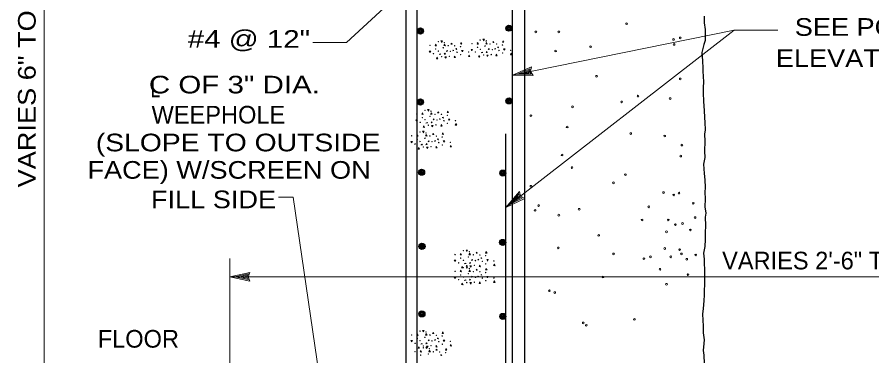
# Model space of a CAD drawing. Extents: x -28.1 to 13.9, y -16.1 to 13.9.
# Drawn here: x -10.39 to -4.33, y -8.27 to -5.87 of the extents above; entities that cross this region are included whole.
import ezdxf
from ezdxf.enums import TextEntityAlignment as Align

# ---------------------------------------------------------------- set-up
doc = ezdxf.new("R2010")
doc.units = 0
doc.header["$LTSCALE"] = 0.05
doc.layers.add('1', color=7, linetype='Continuous', lineweight=13)
doc.layers.add('2', color=7, linetype='Continuous', lineweight=13)

msp = doc.modelspace()

# ---------------------------------------------------------------- linework, layer by layer
at = {"layer": '1', "lineweight": 25}
for p, q in [((-7.63204, -10.78531), (-7.63204, -2.71131)), ((-6.79104, -10.78531), (-6.79104, -2.71131)), ((-6.87804, -10.71531), (-6.87804, -2.77031)), ((-7.55404, -10.70931), (-7.55404, -2.79231)), ((-6.92404, -10.72031), (-6.92404, -6.69531))]:
    msp.add_line(p, q, dxfattribs=at)
at = {"layer": '1'}
for p, q in [((-6.87804, -6.28131), (-5.30604, -5.96131)), ((-6.87804, -6.28131), (-6.74304, -6.22231)), ((-6.84204, -6.27431), (-6.75404, -6.23531)), ((-6.75404, -6.23531), (-6.75804, -6.25731)), ((-6.87804, -6.28131), (-6.73104, -6.28331)), ((-6.84204, -6.27431), (-6.74604, -6.27431)), ((-6.80604, -6.26631), (-6.76404, -6.24831)), ((-6.80604, -6.26631), (-6.76104, -6.26631)), ((-6.76404, -6.24831), (-6.76604, -6.25831)), ((-6.76604, -6.25831), (-6.76104, -6.26631)), ((-6.75804, -6.25731), (-6.74604, -6.27431)), ((-8.53504, -7.14431), (-8.43204, -7.14431)), ((-8.43204, -7.14431), (-8.06504, -9.66431)), ((-6.92404, -7.21731), (-6.82904, -7.10431)), ((-6.89504, -7.19431), (-6.83304, -7.12131)), ((-6.86604, -7.17231), (-6.83704, -7.13731)), ((-6.83704, -7.13731), (-6.83404, -7.14731)), ((-6.83404, -7.14731), (-6.82504, -7.15231)), ((-6.83304, -7.12131), (-6.82804, -7.14231)), ((-6.82804, -7.14231), (-6.80804, -7.15231)), ((-6.92404, -7.21731), (-6.79104, -7.15331)), ((-6.89504, -7.19431), (-6.80804, -7.15231)), ((-6.86604, -7.17231), (-6.82504, -7.15231)), ((-8.88204, -10.58231), (-8.88204, -7.58031)), ((-8.88204, -7.70831), (-8.73804, -7.67731)), ((-8.84504, -7.70831), (-8.75104, -7.68831)), ((-8.75104, -7.68831), (-8.76004, -7.70831)), ((-8.88204, -7.70831), (-2.77004, -7.70831)), ((-8.88204, -7.70831), (-8.73804, -7.73931)), ((-8.84504, -7.70831), (-8.75104, -7.72831)), ((-8.80904, -7.70831), (-8.76404, -7.69831)), ((-8.80904, -7.70831), (-8.76404, -7.71731)), ((-8.76404, -7.69831), (-8.76804, -7.70831)), ((-8.76804, -7.70831), (-8.76404, -7.71731)), ((-8.76004, -7.70831), (-8.75104, -7.72831))]:
    msp.add_line(p, q, dxfattribs=at)
for points in [[(-10.19604, -11.70431), (-10.19604, -9.90431), (-10.19604, -2.71031)], [(-8.29204, -6.04931), (-8.05404, -6.04931), (-7.55404, -5.58731), (-7.63904, -5.70731)], [(-6.92404, -7.21731), (-5.30604, -5.96131), (-4.99804, -5.96131)], [(-6.74304, -6.22231), (-6.75104, -6.25531), (-6.73104, -6.28331)], [(-6.82904, -7.10431), (-6.82104, -7.13731), (-6.79104, -7.15331)], [(-8.73804, -7.67731), (-8.75204, -7.70831), (-8.73804, -7.73931)]]:
    msp.add_lwpolyline(points, dxfattribs=at)
at = {"layer": '1', "lineweight": 25}
for points in [[(-5.52004, -5.86431), (-5.51904, -5.90931), (-5.51304, -5.95831), (-5.51204, -5.99531), (-5.51204, -6.03531), (-5.52204, -6.06331), (-5.53504, -6.12031), (-5.53104, -6.17831), (-5.52904, -6.23031), (-5.52904, -6.25231)], [(-5.52904, -6.25231), (-5.52304, -6.32731), (-5.52604, -6.36831), (-5.52504, -6.40631), (-5.52304, -6.46731), (-5.51904, -6.53231), (-5.51704, -6.58031), (-5.51504, -6.61731), (-5.51204, -6.66831), (-5.51604, -6.69931), (-5.51504, -6.74831), (-5.51604, -6.82031), (-5.51504, -6.86431), (-5.52304, -6.91131), (-5.52004, -6.97631), (-5.51404, -7.02131), (-5.51204, -7.07631), (-5.51404, -7.10831), (-5.51304, -7.15631), (-5.51404, -7.21231), (-5.50804, -7.25931), (-5.51104, -7.28631), (-5.51004, -7.34631), (-5.51204, -7.39731), (-5.51204, -7.44531), (-5.51504, -7.49331), (-5.52304, -7.54131), (-5.51904, -7.58431), (-5.51804, -7.62031), (-5.51604, -7.65331), (-5.51704, -7.70831), (-5.51704, -7.76231), (-5.51804, -7.80631), (-5.52004, -7.83631), (-5.52204, -7.87931), (-5.52704, -7.93331), (-5.53004, -7.97331), (-5.52904, -8.01531), (-5.52704, -8.05831), (-5.52704, -8.10531), (-5.52004, -8.15431), (-5.52204, -8.18131), (-5.52604, -8.23131), (-5.52204, -8.26331), (-5.52004, -8.32331)]]:
    msp.add_lwpolyline(points, dxfattribs=at)
for centre, radius in [((-6.90299, -5.94823), 0.02168), ((-6.90299, -5.94823), 0.01681), ((-6.90299, -5.94823), 0.01233), ((-7.52999, -5.96823), 0.02168), ((-7.52999, -5.96823), 0.01681), ((-7.52999, -5.96823), 0.01233), ((-7.52999, -5.96823), 0.00623), ((-6.90299, -5.94823), 0.00623), ((-7.52999, -6.47123), 0.02168), ((-7.52999, -6.47123), 0.01681), ((-7.52999, -6.47123), 0.01233), ((-7.52999, -6.47123), 0.00623), ((-6.90199, -6.46323), 0.02168), ((-6.90199, -6.46323), 0.01681), ((-6.90199, -6.46323), 0.01233), ((-6.90199, -6.46323), 0.00623), ((-7.52199, -6.96823), 0.02168), ((-7.52199, -6.96823), 0.01681), ((-7.52199, -6.96823), 0.01233), ((-7.52199, -6.96823), 0.00623), ((-6.94599, -6.97423), 0.02168), ((-6.94599, -6.97423), 0.01681), ((-6.94599, -6.97423), 0.01233), ((-6.94599, -6.97423), 0.00623), ((-6.94699, -7.46523), 0.02168), ((-6.94699, -7.46523), 0.01681), ((-7.51899, -7.49323), 0.02168), ((-7.51899, -7.49323), 0.01681), ((-7.51899, -7.49323), 0.01233), ((-7.51899, -7.49323), 0.00623), ((-6.94699, -7.46523), 0.01233), ((-6.94699, -7.46523), 0.00623), ((-7.51999, -7.97123), 0.02168), ((-7.51999, -7.97123), 0.01681), ((-7.51999, -7.97123), 0.01233), ((-7.51999, -7.97123), 0.00623), ((-6.94599, -7.98923), 0.02168), ((-6.94599, -7.98923), 0.01681), ((-6.94599, -7.98923), 0.01233), ((-6.94599, -7.98923), 0.00623)]:
    msp.add_circle(centre, radius, dxfattribs=at)
at = {"layer": '1'}
for centre in [(-6.06904, -5.91631), (-6.71204, -5.97431), (-6.54904, -5.97431), (-5.73604, -6.02831), (-5.73204, -6.06331), (-5.68904, -6.01731), (-6.57204, -6.11031), (-6.32404, -6.07931), (-6.28204, -6.28831), (-5.68904, -6.30731), (-6.10404, -6.47031), (-5.98804, -6.42931), (-5.76004, -6.44631), (-6.45204, -6.50531), (-6.74704, -6.56731), (-6.49004, -6.64831), (-6.03904, -6.69431), (-5.79804, -6.71131), (-5.67704, -6.77631), (-6.52604, -6.84631), (-5.68504, -6.85431), (-6.45604, -6.93531), (-6.07704, -6.98531), (-6.74704, -7.06731), (-6.16204, -7.04331), (-5.80704, -7.11231), (-5.73504, -7.12931), (-5.69704, -7.11631), (-6.69204, -7.20431), (-5.91204, -7.21331), (-5.59604, -7.18831), (-6.71704, -7.23831), (-6.54904, -7.27231), (-6.40504, -7.23031), (-5.95904, -7.30631), (-5.77304, -7.30631), (-5.67204, -7.33131), (-5.58304, -7.28931), (-5.78604, -7.39031), (-5.72304, -7.33931), (-5.61704, -7.37731), (-6.26604, -7.41531), (-6.55304, -7.50431), (-5.79804, -7.50831), (-5.69304, -7.51631), (-6.16104, -7.54631), (-5.90004, -7.56731), (-5.75604, -7.56731), (-5.68004, -7.54631), (-5.57904, -7.55431), (-5.94604, -7.58031), (-5.64204, -7.58431), (-5.83204, -7.65531), (-5.63404, -7.69331), (-6.23704, -7.71031), (-6.61604, -7.80731), (-6.57804, -7.82031), (-5.78604, -7.76131), (-6.37604, -8.03531), (-6.35504, -8.05231), (-6.01304, -8.01031)]:
    msp.add_circle(centre, 0.006, dxfattribs=at)
at = {"layer": '2'}
for p, q in [((-7.31404, -6.05931), (-7.30804, -6.05431)), ((-7.01704, -6.04731), (-7.01104, -6.04231)), ((-7.40804, -6.54531), (-7.40204, -6.54031)), ((-7.44404, -6.69931), (-7.43804, -6.69431)), ((-7.13604, -7.54031), (-7.13004, -7.53531)), ((-7.13604, -7.65931), (-7.13004, -7.65431)), ((-7.44404, -8.10931), (-7.43804, -8.10431)), ((-7.42004, -8.22731), (-7.41404, -8.22231))]:
    msp.add_line(p, q, dxfattribs=at)
for points in [[(-7.38004, -6.04731), (-7.38504, -6.03831), (-7.37404, -6.03831), (-7.38004, -6.04931)], [(-7.30804, -6.05431), (-7.30604, -6.06131), (-7.31404, -6.06131)], [(-7.24104, -6.04931), (-7.24604, -6.05931), (-7.23604, -6.06031), (-7.24404, -6.04931)], [(-7.12404, -6.05031), (-7.12904, -6.06031), (-7.11904, -6.06131), (-7.12704, -6.05031)], [(-7.08304, -6.03531), (-7.08804, -6.02631), (-7.07704, -6.02631), (-7.08304, -6.03731)], [(-7.06204, -6.04931), (-7.06704, -6.05931), (-7.05604, -6.06031), (-7.06404, -6.04931)], [(-7.01104, -6.04231), (-7.00904, -6.04931), (-7.01704, -6.04931)], [(-6.94404, -6.03731), (-6.94904, -6.04731), (-6.93904, -6.04831), (-6.94704, -6.03731)], [(-7.46304, -6.11831), (-7.46804, -6.11031), (-7.45704, -6.11031), (-7.46304, -6.12031)], [(-7.42104, -6.06231), (-7.42604, -6.07231), (-7.41604, -6.07331), (-7.42404, -6.06231)], [(-7.35904, -6.06131), (-7.36404, -6.07131), (-7.35304, -6.07231), (-7.36104, -6.06131)], [(-7.30104, -6.10731), (-7.29804, -6.10331), (-7.29304, -6.10731), (-7.30004, -6.10831)], [(-7.28104, -6.09431), (-7.27604, -6.09231), (-7.27304, -6.09831), (-7.28104, -6.09531)], [(-7.23304, -6.11431), (-7.23804, -6.10631), (-7.22704, -6.10631), (-7.23304, -6.11631)], [(-7.16604, -6.10631), (-7.17104, -6.09831), (-7.16004, -6.09831), (-7.16604, -6.10831)], [(-7.09704, -6.12131), (-7.09204, -6.11831), (-7.08804, -6.12131), (-7.10004, -6.12331)], [(-7.00404, -6.09531), (-7.00104, -6.09131), (-6.99604, -6.09531), (-7.00304, -6.09631)], [(-6.98404, -6.08231), (-6.97904, -6.08031), (-6.97604, -6.08631), (-6.98404, -6.08331)], [(-6.93604, -6.10231), (-6.94104, -6.09431), (-6.93004, -6.09431), (-6.93604, -6.10431)], [(-7.41104, -6.15431), (-7.41604, -6.16431), (-7.40604, -6.16531), (-7.41404, -6.15431)], [(-7.39404, -6.13331), (-7.38904, -6.13031), (-7.38504, -6.13331), (-7.39704, -6.13531)], [(-7.35204, -6.15931), (-7.35704, -6.15031), (-7.34604, -6.15031), (-7.35204, -6.16031)], [(-7.28704, -6.14531), (-7.29204, -6.15531), (-7.28204, -6.15631), (-7.29004, -6.14531)], [(-7.18404, -6.13831), (-7.18904, -6.14831), (-7.17904, -6.14931), (-7.18604, -6.13831)], [(-7.11404, -6.14231), (-7.11904, -6.15231), (-7.10904, -6.15331), (-7.11704, -6.14231)], [(-7.05504, -6.14731), (-7.06004, -6.13831), (-7.04904, -6.13831), (-7.05504, -6.14831)], [(-6.99004, -6.13331), (-6.99504, -6.14331), (-6.98504, -6.14431), (-6.99304, -6.13331)], [(-6.88704, -6.12631), (-6.89204, -6.13631), (-6.88204, -6.13731), (-6.88904, -6.12631)], [(-7.47404, -6.53331), (-7.47904, -6.52431), (-7.46804, -6.52431), (-7.47404, -6.53531)], [(-7.40204, -6.54031), (-7.40004, -6.54731), (-7.40804, -6.54731)], [(-7.33504, -6.53531), (-7.34004, -6.54531), (-7.33004, -6.54631), (-7.33804, -6.53531)], [(-7.55704, -6.60431), (-7.56204, -6.59631), (-7.55104, -6.59631), (-7.55704, -6.60631)], [(-7.51504, -6.54831), (-7.52004, -6.55831), (-7.51004, -6.55931), (-7.51804, -6.54831)], [(-7.45304, -6.54731), (-7.45804, -6.55731), (-7.44704, -6.55831), (-7.45504, -6.54731)], [(-7.39504, -6.59331), (-7.39204, -6.58931), (-7.38704, -6.59331), (-7.39404, -6.59431)], [(-7.37504, -6.58031), (-7.37004, -6.57831), (-7.36704, -6.58431), (-7.37504, -6.58131)], [(-7.32704, -6.60031), (-7.33204, -6.59231), (-7.32104, -6.59231), (-7.32704, -6.60231)], [(-7.50504, -6.64031), (-7.51004, -6.65031), (-7.50004, -6.65131), (-7.50804, -6.64031)], [(-7.48804, -6.61931), (-7.48304, -6.61631), (-7.47904, -6.61931), (-7.49104, -6.62131)], [(-7.44604, -6.64531), (-7.45104, -6.63631), (-7.44004, -6.63631), (-7.44604, -6.64631)], [(-7.38104, -6.63131), (-7.38604, -6.64131), (-7.37604, -6.64231), (-7.38404, -6.63131)], [(-7.27804, -6.62431), (-7.28304, -6.63431), (-7.27304, -6.63531), (-7.28004, -6.62431)], [(-7.55104, -6.70231), (-7.55604, -6.71231), (-7.54604, -6.71331), (-7.55404, -6.70231)], [(-7.51004, -6.68731), (-7.51504, -6.67831), (-7.50404, -6.67831), (-7.51004, -6.68931)], [(-7.48904, -6.70131), (-7.49404, -6.71131), (-7.48304, -6.71231), (-7.49104, -6.70131)], [(-7.43804, -6.69431), (-7.43604, -6.70131), (-7.44404, -6.70131)], [(-7.37104, -6.68931), (-7.37604, -6.69931), (-7.36604, -6.70031), (-7.37404, -6.68931)], [(-7.59304, -6.75831), (-7.59804, -6.75031), (-7.58704, -6.75031), (-7.59304, -6.76031)], [(-7.52404, -6.77331), (-7.51904, -6.77031), (-7.51504, -6.77331), (-7.52704, -6.77531)], [(-7.43104, -6.74731), (-7.42804, -6.74331), (-7.42304, -6.74731), (-7.43004, -6.74831)], [(-7.41704, -6.78531), (-7.42204, -6.79531), (-7.41204, -6.79631), (-7.42004, -6.78531)], [(-7.41104, -6.73431), (-7.40604, -6.73231), (-7.40304, -6.73831), (-7.41104, -6.73531)], [(-7.36304, -6.75431), (-7.36804, -6.74631), (-7.35704, -6.74631), (-7.36304, -6.75631)], [(-7.31404, -6.77831), (-7.31904, -6.78831), (-7.30904, -6.78931), (-7.31604, -6.77831)], [(-7.54104, -6.79431), (-7.54604, -6.80431), (-7.53604, -6.80531), (-7.54404, -6.79431)], [(-7.48204, -6.79931), (-7.48704, -6.79031), (-7.47604, -6.79031), (-7.48204, -6.80031)], [(-7.24304, -7.54331), (-7.24804, -7.55331), (-7.23804, -7.55431), (-7.24604, -7.54331)], [(-7.20204, -7.52831), (-7.20704, -7.51931), (-7.19604, -7.51931), (-7.20204, -7.53031)], [(-7.18104, -7.54231), (-7.18604, -7.55231), (-7.17504, -7.55331), (-7.18304, -7.54231)], [(-7.13004, -7.53531), (-7.12804, -7.54231), (-7.13604, -7.54231)], [(-7.06304, -7.53031), (-7.06804, -7.54031), (-7.05804, -7.54131), (-7.06604, -7.53031)], [(-7.28504, -7.59931), (-7.29004, -7.59131), (-7.27904, -7.59131), (-7.28504, -7.60131)], [(-7.21604, -7.61431), (-7.21104, -7.61131), (-7.20704, -7.61431), (-7.21904, -7.61631)], [(-7.17404, -7.64031), (-7.17904, -7.63131), (-7.16804, -7.63131), (-7.17404, -7.64131)], [(-7.12304, -7.58831), (-7.12004, -7.58431), (-7.11504, -7.58831), (-7.12204, -7.58931)], [(-7.10904, -7.62631), (-7.11404, -7.63631), (-7.10404, -7.63731), (-7.11204, -7.62631)], [(-7.10304, -7.57531), (-7.09804, -7.57331), (-7.09504, -7.57931), (-7.10304, -7.57631)], [(-7.05504, -7.59531), (-7.06004, -7.58731), (-7.04904, -7.58731), (-7.05504, -7.59731)], [(-7.00604, -7.61931), (-7.01104, -7.62931), (-7.00104, -7.63031), (-7.00804, -7.61931)], [(-7.24304, -7.66231), (-7.24804, -7.67231), (-7.23804, -7.67331), (-7.24604, -7.66231)], [(-7.23304, -7.63531), (-7.23804, -7.64531), (-7.22804, -7.64631), (-7.23604, -7.63531)], [(-7.20204, -7.64731), (-7.20704, -7.63831), (-7.19604, -7.63831), (-7.20204, -7.64931)], [(-7.18104, -7.66131), (-7.18604, -7.67131), (-7.17504, -7.67231), (-7.18304, -7.66131)], [(-7.13004, -7.65431), (-7.12804, -7.66131), (-7.13604, -7.66131)], [(-7.10304, -7.69431), (-7.09804, -7.69231), (-7.09504, -7.69831), (-7.10304, -7.69531)], [(-7.06304, -7.64931), (-7.06804, -7.65931), (-7.05804, -7.66031), (-7.06604, -7.64931)], [(-7.28504, -7.71831), (-7.29004, -7.71031), (-7.27904, -7.71031), (-7.28504, -7.72031)], [(-7.23304, -7.75431), (-7.23804, -7.76431), (-7.22804, -7.76531), (-7.23604, -7.75431)], [(-7.21604, -7.73331), (-7.21104, -7.73031), (-7.20704, -7.73331), (-7.21904, -7.73531)], [(-7.17404, -7.75931), (-7.17904, -7.75031), (-7.16804, -7.75031), (-7.17404, -7.76031)], [(-7.12304, -7.70731), (-7.12004, -7.70331), (-7.11504, -7.70731), (-7.12204, -7.70831)], [(-7.10904, -7.74531), (-7.11404, -7.75531), (-7.10404, -7.75631), (-7.11204, -7.74531)], [(-7.05504, -7.71431), (-7.06004, -7.70631), (-7.04904, -7.70631), (-7.05504, -7.71631)], [(-7.00604, -7.73831), (-7.01104, -7.74831), (-7.00104, -7.74931), (-7.00804, -7.73831)], [(-7.55104, -8.11231), (-7.55604, -8.12231), (-7.54604, -8.12331), (-7.55404, -8.11231)], [(-7.51004, -8.09731), (-7.51504, -8.08831), (-7.50404, -8.08831), (-7.51004, -8.09931)], [(-7.48904, -8.11131), (-7.49404, -8.12131), (-7.48304, -8.12231), (-7.49104, -8.11131)], [(-7.43804, -8.10431), (-7.43604, -8.11131), (-7.44404, -8.11131)], [(-7.37104, -8.09931), (-7.37604, -8.10931), (-7.36604, -8.11031), (-7.37404, -8.09931)], [(-7.59304, -8.16831), (-7.59804, -8.16031), (-7.58704, -8.16031), (-7.59304, -8.17031)], [(-7.43104, -8.15731), (-7.42804, -8.15331), (-7.42304, -8.15731), (-7.43004, -8.15831)], [(-7.41104, -8.14431), (-7.40604, -8.14231), (-7.40304, -8.14831), (-7.41104, -8.14531)], [(-7.36304, -8.16431), (-7.36804, -8.15631), (-7.35704, -8.15631), (-7.36304, -8.16631)], [(-7.54104, -8.20431), (-7.54604, -8.21431), (-7.53604, -8.21531), (-7.54404, -8.20431)], [(-7.52704, -8.23031), (-7.53204, -8.24031), (-7.52204, -8.24131), (-7.53004, -8.23031)], [(-7.52404, -8.18331), (-7.51904, -8.18031), (-7.51504, -8.18331), (-7.52704, -8.18531)], [(-7.48604, -8.21531), (-7.49104, -8.20631), (-7.48004, -8.20631), (-7.48604, -8.21731)], [(-7.48204, -8.20931), (-7.48704, -8.20031), (-7.47604, -8.20031), (-7.48204, -8.21031)], [(-7.46504, -8.22931), (-7.47004, -8.23931), (-7.45904, -8.24031), (-7.46704, -8.22931)], [(-7.41704, -8.19531), (-7.42204, -8.20531), (-7.41204, -8.20631), (-7.42004, -8.19531)], [(-7.41404, -8.22231), (-7.41204, -8.22931), (-7.42004, -8.22931)], [(-7.34704, -8.21731), (-7.35204, -8.22731), (-7.34204, -8.22831), (-7.35004, -8.21731)], [(-7.31404, -8.18831), (-7.31904, -8.19831), (-7.30904, -8.19931), (-7.31604, -8.18831)], [(-7.38704, -8.26231), (-7.38204, -8.26031), (-7.37904, -8.26631), (-7.38704, -8.26331)]]:
    msp.add_lwpolyline(points, dxfattribs=at)
for points in [[(-7.34604, -6.11231), (-7.34104, -6.10331), (-7.33804, -6.10931)], [(-7.06404, -6.12131), (-7.05904, -6.11331), (-7.05604, -6.11931)], [(-7.04904, -6.10031), (-7.04404, -6.09131), (-7.04104, -6.09731)], [(-7.36104, -6.13331), (-7.35604, -6.12531), (-7.35304, -6.13131)], [(-7.44004, -6.59831), (-7.43504, -6.58931), (-7.43204, -6.59531)], [(-7.45504, -6.61931), (-7.45004, -6.61131), (-7.44704, -6.61731)], [(-7.49104, -6.77331), (-7.48604, -6.76531), (-7.48304, -6.77131)], [(-7.47604, -6.75231), (-7.47104, -6.74331), (-7.46804, -6.74931)], [(-7.18304, -7.61431), (-7.17804, -7.60631), (-7.17504, -7.61231)], [(-7.16804, -7.59331), (-7.16304, -7.58431), (-7.16004, -7.59031)], [(-7.18304, -7.73331), (-7.17804, -7.72531), (-7.17504, -7.73131)], [(-7.16804, -7.71231), (-7.16304, -7.70331), (-7.16004, -7.70931)], [(-7.49104, -8.18331), (-7.48604, -8.17531), (-7.48304, -8.18131)], [(-7.47604, -8.16231), (-7.47104, -8.15331), (-7.46804, -8.15931)]]:
    msp.add_lwpolyline(points, close=True, dxfattribs=at)
for centre in [(-7.40379, -6.04344), (-7.36104, -6.05019), (-7.16504, -6.05819), (-7.10679, -6.03144), (-7.06404, -6.03819), (-7.03629, -6.05994), (-7.46204, -6.07019), (-7.42229, -6.09544), (-7.40304, -6.11069), (-7.36854, -6.08719), (-7.33329, -6.07194), (-7.31804, -6.11244), (-7.28704, -6.07294), (-7.27004, -6.11819), (-7.24579, -6.07869), (-7.18754, -6.11644), (-7.14054, -6.11719), (-7.12529, -6.08344), (-7.10604, -6.09869), (-7.07154, -6.07519), (-7.02104, -6.10044), (-6.99004, -6.06094), (-6.97304, -6.10619), (-6.94879, -6.06669), (-6.89054, -6.10444), (-7.43754, -6.12919), (-7.37954, -6.14944), (-7.32554, -6.14694), (-7.24479, -6.13594), (-7.08254, -6.13744), (-7.02854, -6.13494), (-6.94779, -6.12394), (-7.49779, -6.52944), (-7.45504, -6.53619), (-7.55604, -6.55619), (-7.51629, -6.58144), (-7.49704, -6.59669), (-7.46254, -6.57319), (-7.42729, -6.55794), (-7.41204, -6.59844), (-7.38104, -6.55894), (-7.36404, -6.60419), (-7.33979, -6.56469), (-7.28154, -6.60244), (-7.53154, -6.61519), (-7.47354, -6.63544), (-7.41954, -6.63294), (-7.33879, -6.62194), (-7.59204, -6.71019), (-7.53379, -6.68344), (-7.49104, -6.69019), (-7.46329, -6.71194), (-7.41704, -6.71294), (-7.37579, -6.71869), (-7.56754, -6.76919), (-7.55229, -6.73544), (-7.53304, -6.75069), (-7.49854, -6.72719), (-7.45554, -6.78694), (-7.44804, -6.75244), (-7.40004, -6.75819), (-7.37479, -6.77594), (-7.31754, -6.75644), (-7.50954, -6.78944), (-7.28404, -7.55119), (-7.22579, -7.52444), (-7.19054, -7.56819), (-7.18304, -7.53119), (-7.15529, -7.55294), (-7.10904, -7.55394), (-7.06779, -7.55969), (-7.25954, -7.61019), (-7.24429, -7.57644), (-7.22504, -7.59169), (-7.20154, -7.63044), (-7.14754, -7.62794), (-7.14004, -7.59344), (-7.09204, -7.59919), (-7.06679, -7.61694), (-7.00954, -7.59744), (-7.28404, -7.67019), (-7.24429, -7.69544), (-7.22579, -7.64344), (-7.19054, -7.68719), (-7.18304, -7.65019), (-7.15529, -7.67194), (-7.10904, -7.67294), (-7.06779, -7.67869), (-7.25954, -7.72919), (-7.22504, -7.71069), (-7.20154, -7.74944), (-7.14754, -7.74694), (-7.14004, -7.71244), (-7.09204, -7.71819), (-7.06679, -7.73594), (-7.00954, -7.71644), (-7.53379, -8.09344), (-7.49104, -8.10019), (-7.59204, -8.12019), (-7.56754, -8.17919), (-7.55229, -8.14544), (-7.53304, -8.16069), (-7.49854, -8.13719), (-7.46329, -8.12194), (-7.44804, -8.16244), (-7.41704, -8.12294), (-7.40004, -8.16819), (-7.37579, -8.12869), (-7.31754, -8.16644), (-7.56804, -8.23819), (-7.50979, -8.21144), (-7.50954, -8.19944), (-7.46704, -8.21819), (-7.45554, -8.19694), (-7.43929, -8.23994), (-7.39304, -8.24094), (-7.37479, -8.18594), (-7.52829, -8.26344), (-7.47454, -8.25519), (-7.35179, -8.24669)]:
    msp.add_circle(centre, 0.00162, dxfattribs=at)

# ---------------------------------------------------------------- texts
at = {"layer": '1', "width": 1.15}
msp.add_text('VARIES 6" TO 17\'-9 1/2"', height=0.125, rotation=90, dxfattribs=at).set_placement((-10.25704, -6.01675), align=Align.CENTER)
at = {"layer": '1'}
for s, width, p in [('SEE PORTAL WALL', 1.15, (-4.87704, -6.00231)), ('L', 0.75, (-9.44304, -6.43731))]:
    msp.add_text(s, height=0.125, dxfattribs=dict(at, width=width)).set_placement(p)
for s, width, p in [('#4 @ 12"', 1.25, (-8.74548, -6.08731)), ('ELEVATION, SHEET 2', 1.15, (-4.01748, -6.22331)), ('C OF 3" DIA.', 1.25, (-8.84867, -6.41031)), ('(SLOPE TO OUTSIDE', 1.2, (-8.82236, -6.82031)), ('FACE) W/SCREEN ON', 1.15, (-8.88621, -7.01431)), ('FILL SIDE', 1.15, (-8.99654, -7.22331))]:
    msp.add_text(s, height=0.125, dxfattribs=dict(at, width=width)).set_placement(p, align=Align.CENTER)
for s, p in [('WEEPHOLE', (-8.96189, -6.62331)), ('VARIES 2\'-6" TO 12\'-0"', (-4.52025, -7.65631)), ('FLOOR', (-9.52929, -8.21031))]:
    msp.add_text(s, height=0.125, dxfattribs=at).set_placement(p, align=Align.CENTER)

doc.saveas('drawing.dxf')
